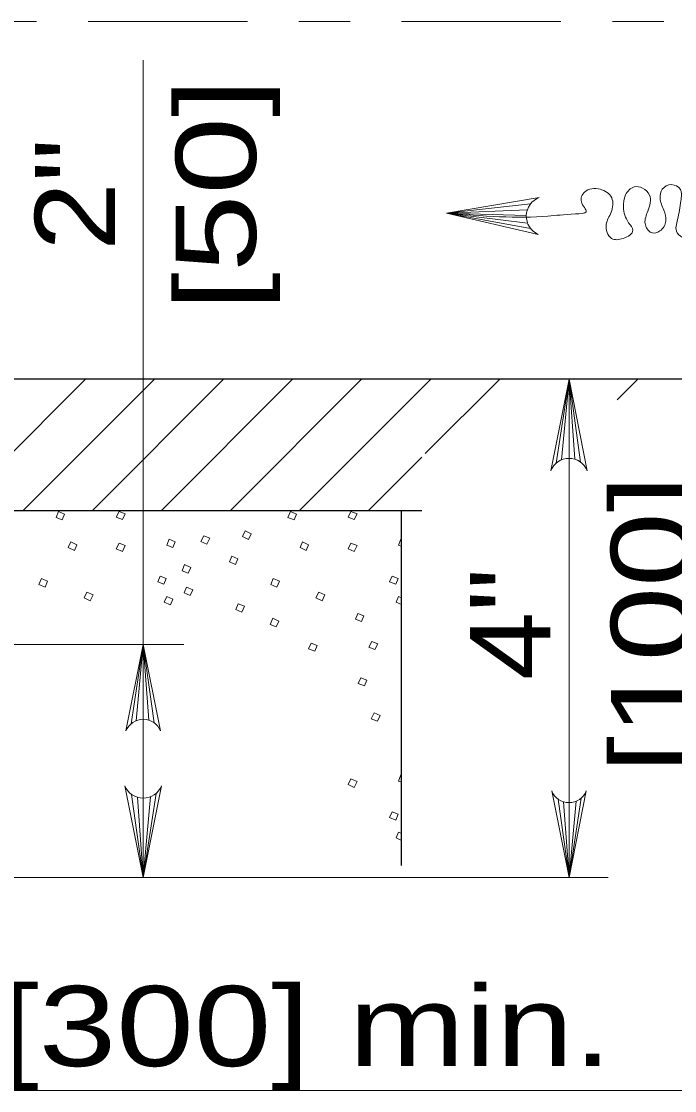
# Model space of a CAD drawing. Extents: x 1083.1 to 1117.1, y 719.4 to 741.4.
# Drawn here: x 1103.751 to 1105.022, y 725.359 to 727.439 of the extents above; entities that cross this region are included whole.
import ezdxf
from ezdxf.enums import TextEntityAlignment as Align

# ---------------------------------------------------------------- set-up
doc = ezdxf.new("R2010")
doc.units = 0
doc.header["$LTSCALE"] = 0.062
doc.linetypes.add('DOT_DASHED', pattern=[7.7, 5, -1.2, 0.3, -1.2])
doc.layers.add('1', color=7, linetype='Continuous', lineweight=13)

msp = doc.modelspace()

# ---------------------------------------------------------------- linework, layer by layer
at = {"layer": '1', "linetype": 'DOT_DASHED'}
msp.add_line((1102.66067, 727.43908), (1107.24233, 727.43908), dxfattribs=at)
at = {"layer": '1'}
for p, q in [((1103.98808, 727.36375), (1103.98808, 725.77383)), ((1104.74125, 727.08383), (1104.578, 727.06617)), ((1104.73533, 727.07267), (1104.578, 727.06617)), ((1104.73333, 727.06125), (1104.578, 727.06617)), ((1104.73575, 727.04658), (1104.578, 727.06617)), ((1104.74158, 727.03583), (1104.578, 727.06617)), ((1103.6205, 726.48767), (1103.87583, 726.743)), ((1103.75475, 726.48767), (1104.01008, 726.743)), ((1103.88908, 726.48767), (1104.14442, 726.743)), ((1104.02333, 726.48767), (1104.27867, 726.743)), ((1104.15758, 726.48767), (1104.413, 726.743)), ((1104.29192, 726.48767), (1104.54725, 726.743)), ((1104.53675, 726.59817), (1104.6815, 726.743)), ((1104.79142, 726.57992), (1104.81642, 726.743)), ((1104.80192, 726.58608), (1104.81642, 726.743)), ((1104.81642, 726.58892), (1104.81642, 726.743)), ((1104.82775, 726.58725), (1104.81642, 726.743)), ((1104.83892, 726.58183), (1104.81642, 726.743)), ((1104.81642, 726.743), (1104.81642, 725.77383)), ((1104.91025, 726.70308), (1104.95008, 726.743)), ((1104.42617, 726.48767), (1104.52992, 726.59142)), ((1104.4895, 726.432), (1104.49067, 726.4315)), ((1104.48475, 726.3205), (1104.49067, 726.31767)), ((1103.34392, 726.22675), (1104.06717, 726.22675)), ((1103.9645, 726.07275), (1103.98808, 726.22675)), ((1103.97442, 726.07858), (1103.98808, 726.22675)), ((1103.98808, 726.08125), (1103.98808, 726.22675)), ((1103.99883, 726.07975), (1103.98808, 726.22675)), ((1104.00933, 726.07458), (1103.98808, 726.22675)), ((1104.4895, 725.97308), (1104.49067, 725.97258)), ((1103.9655, 725.935), (1103.98808, 725.77383)), ((1104.013, 725.93692), (1103.98808, 725.77383)), ((1103.97667, 725.9295), (1103.98808, 725.77383)), ((1104.0025, 725.93075), (1103.98808, 725.77383)), ((1103.98808, 725.92783), (1103.98808, 725.77383)), ((1104.79508, 725.92608), (1104.81642, 725.77383)), ((1104.80558, 725.92092), (1104.81642, 725.77383)), ((1104.83992, 725.92783), (1104.81642, 725.77383)), ((1104.83008, 725.922), (1104.81642, 725.77383)), ((1104.81642, 725.91933), (1104.81642, 725.77383)), ((1104.48475, 725.86158), (1104.49067, 725.85883)), ((1102.832, 725.77383), (1104.89233, 725.77383)), ((1103.53142, 725.35892), (1105.59625, 725.35892))]:
    msp.add_line(p, q, dxfattribs=at)
at = {"layer": '1', "lineweight": 25}
for p, q in [((1104.49067, 725.797), (1104.49067, 726.48767)), ((1104.49067, 726.48767), (1104.52992, 726.48767))]:
    msp.add_line(p, q, dxfattribs=at)
at = {"layer": '1'}
for points in [[(1104.75633, 727.02467), (1104.578, 727.06617), (1104.75858, 727.0965)], [(1104.78075, 726.56492), (1104.81642, 726.743), (1104.852, 726.56492)], [(1104.49067, 726.41775), (1104.48475, 726.42017), (1104.4895, 726.432)], [(1104.49067, 726.30442), (1104.48, 726.30942), (1104.48475, 726.3205)], [(1103.95442, 726.05867), (1103.98808, 726.22675), (1104.02167, 726.05867)], [(1104.49067, 725.95892), (1104.48475, 725.96125), (1104.4895, 725.97308)], [(1104.02367, 725.95183), (1103.98808, 725.77383), (1103.95242, 725.95183)], [(1104.85, 725.942), (1104.81642, 725.77383), (1104.78275, 725.942)], [(1104.49067, 725.8455), (1104.48, 725.8505), (1104.48475, 725.86158)]]:
    msp.add_lwpolyline(points, dxfattribs=at)
at = {"layer": '1', "lineweight": 25}
msp.add_lwpolyline([(1105.59625, 726.743), (1102.779, 726.743), (1102.779, 726.48767), (1103.53142, 726.48767), (1104.49067, 726.48767)], dxfattribs=at)
at = {"layer": '1'}
for points in [[(1103.82325, 726.48583), (1103.83508, 726.48025), (1103.83033, 726.46925), (1103.8185, 726.474)], [(1103.94117, 726.48583), (1103.953, 726.48108), (1103.94742, 726.47), (1103.93558, 726.47475)], [(1104.27425, 726.48583), (1104.28617, 726.48025), (1104.28142, 726.46925), (1104.2695, 726.474)], [(1104.39217, 726.48583), (1104.404, 726.48108), (1104.3985, 726.47), (1104.38658, 726.47475)], [(1104.10575, 726.43833), (1104.11758, 726.43358), (1104.11208, 726.42175), (1104.10017, 726.42725)], [(1104.18642, 726.44783), (1104.19833, 726.44233), (1104.19275, 726.43125), (1104.18092, 726.43675)], [(1103.847, 726.4265), (1103.85883, 726.42092), (1103.85408, 726.40983), (1103.84225, 726.41542)], [(1103.94117, 726.42408), (1103.953, 726.41933), (1103.94742, 726.4075), (1103.93558, 726.413)], [(1104.03842, 726.432), (1104.05033, 726.4265), (1104.04558, 726.41542), (1104.03375, 726.42017)], [(1104.298, 726.4265), (1104.30983, 726.42092), (1104.30508, 726.40983), (1104.29325, 726.41542)], [(1104.39217, 726.42408), (1104.404, 726.41933), (1104.3985, 726.4075), (1104.38658, 726.413)], [(1104.16033, 726.39883), (1104.17217, 726.39325), (1104.16742, 726.38217), (1104.15558, 726.38775)], [(1104.0685, 726.38217), (1104.08042, 726.37667), (1104.07567, 726.36558), (1104.06375, 726.37033)], [(1103.79, 726.35525), (1103.80183, 726.34975), (1103.79708, 726.33867), (1103.78525, 726.34342)], [(1104.02108, 726.36), (1104.03292, 726.35525), (1104.02817, 726.34417), (1104.01633, 726.34892)], [(1104.241, 726.35525), (1104.25292, 726.34975), (1104.24817, 726.33867), (1104.23625, 726.34342)], [(1104.47208, 726.36), (1104.48392, 726.35525), (1104.47917, 726.34417), (1104.46733, 726.34892)], [(1104.0725, 726.33867), (1104.08433, 726.33317), (1104.07958, 726.32208), (1104.06775, 726.32758)], [(1103.87858, 726.32842), (1103.8905, 726.32367), (1103.88492, 726.31175), (1103.87308, 726.31733)], [(1104.03375, 726.3205), (1104.04558, 726.31492), (1104.04083, 726.30383), (1104.02892, 726.30942)], [(1104.32967, 726.32842), (1104.3415, 726.32367), (1104.336, 726.31175), (1104.32408, 726.31733)], [(1104.173, 726.30625), (1104.18483, 726.3015), (1104.18008, 726.28958), (1104.16825, 726.29517)], [(1104.24025, 726.27775), (1104.25208, 726.27217), (1104.24658, 726.26117), (1104.23467, 726.26583)], [(1104.40558, 726.28725), (1104.4175, 726.2825), (1104.41275, 726.27142), (1104.40083, 726.27617)], [(1104.31458, 726.2295), (1104.3265, 726.22475), (1104.32175, 726.21367), (1104.30983, 726.21842)], [(1104.4325, 726.23267), (1104.44442, 726.22792), (1104.43883, 726.21683), (1104.427, 726.22158)], [(1104.41117, 726.16225), (1104.423, 726.1575), (1104.41825, 726.14642), (1104.40642, 726.15117)], [(1104.43725, 726.09417), (1104.44917, 726.08867), (1104.44358, 726.07758), (1104.43175, 726.08233)], [(1104.39217, 725.96525), (1104.404, 725.9605), (1104.3985, 725.94858), (1104.38658, 725.95417)], [(1104.47208, 725.90117), (1104.48392, 725.89642), (1104.47917, 725.88533), (1104.46733, 725.89008)]]:
    msp.add_lwpolyline(points, close=True, dxfattribs=at)
for centre, start, end in [((1103.98809, 726.04506), 22.08782, 157.91395), ((1104.81634, 725.95555), 202.08782, 337.91395)]:
    msp.add_arc(centre, 0.03629, start, end, dxfattribs=at)
for centre, major_axis, start_param, end_param in [((1104.77202, 727.06008), (-0.03875, 0), 5.0665441, 7.4371572), ((1104.81638, 726.5505), (0.03843, 0), 0.3855052, 2.7561184), ((1103.98805, 725.96629), (-0.03843, 0), 0.3855052, 2.7561184)]:
    msp.add_ellipse(centre, major_axis=major_axis, ratio=0.999895, start_param=start_param, end_param=end_param, dxfattribs=at)
msp.add_spline([(1105.22533, 727.09058), (1105.07008, 727.08192), (1105.07308, 727.05042), (1105.06683, 727.03467), (1105.04192, 727.01783), (1105.0265, 727.028), (1105.02758, 727.05392), (1105.03392, 727.08983), (1105.033, 727.11233), (1105.01542, 727.12142), (1104.99783, 727.11242), (1104.99358, 727.09558), (1105.00075, 727.07183), (1105.00483, 727.05058), (1104.99325, 727.03142), (1104.97675, 727.02808), (1104.96442, 727.04617), (1104.96967, 727.06975), (1104.97292, 727.10125), (1104.95958, 727.11475), (1104.943, 727.11708), (1104.92633, 727.10133), (1104.92217, 727.07775), (1104.93233, 727.04725), (1104.94058, 727.03258), (1104.92183, 727.01692), (1104.89908, 727.01692), (1104.88883, 727.044), (1104.89825, 727.06767), (1104.89942, 727.09575), (1104.87683, 727.11258), (1104.84675, 727.10708), (1104.84042, 727.088), (1104.84958, 727.06883), (1104.82883, 727.06442), (1104.77508, 727.06), (1104.578, 727.06617)], degree=3, dxfattribs=at)

# ---------------------------------------------------------------- texts
for s, width, p in [('[50]', 1.3, (1104.20725, 727.10213)), ('2"', 1.15, (1103.93325, 727.10213)), ('[100]', 1.25, (1105.05383, 726.26642)), ('4"', 1.15, (1104.77983, 726.26642))]:
    msp.add_text(s, height=0.156, rotation=90, dxfattribs=dict(at, width=width)).set_placement(p, align=Align.CENTER)
at = {"layer": '1', "width": 1.3}
msp.add_text('12" [300] min.', height=0.156, dxfattribs=at).set_placement((1103.23617, 725.40658))

doc.saveas('drawing.dxf')
